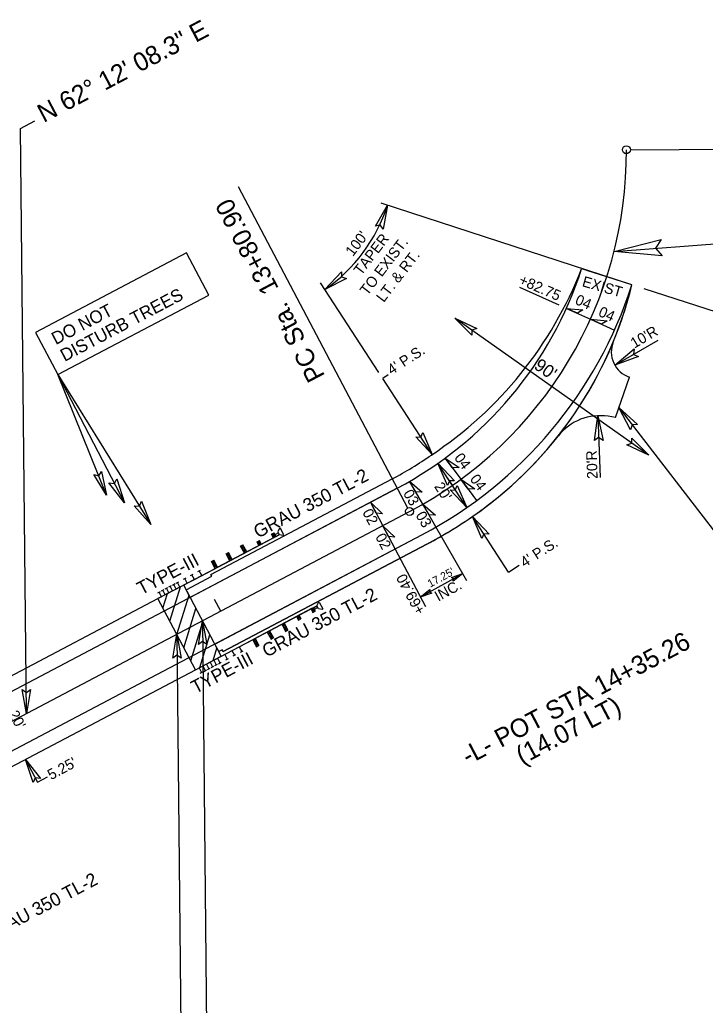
# Model space of a CAD drawing. Extents: x 1380803 to 1382221, y 595175 to 595787.
# Drawn here: x 1381652.6 to 1381912.3, y 595407.2 to 595780.6 of the extents above; entities that cross this region are included whole.
import ezdxf

# ---------------------------------------------------------------- set-up
doc = ezdxf.new("R2010")
doc.units = 0
for name, color, linetype in [('Prop Approach Slab', 7, 'Continuous'), ('Prop Approach Slab Hatching', 7, 'Continuous'), ('Prop DGN Element Guardrail', 7, 'Continuous'), ('Prop Dimension', 7, 'Continuous'), ('Prop Dimension Text', 7, 'Continuous'), ('Prop EOT', 7, 'Continuous'), ('Prop Guardrail', 7, 'Continuous'), ('Prop Guardrail Anchor Unit CELL', 7, 'Continuous'), ('Prop Horizontal Alignment', 7, 'Continuous'), ('Prop Horizontal Alignment Direction Label', 7, 'Continuous'), ('Prop Horizontal Alignment Station Label', 7, 'Continuous'), ('Prop Horizontal Alignment Tick Large', 7, 'Continuous'), ('Prop Horizontal Alignment Tick Small', 7, 'Continuous'), ('Prop Paved Shoulder', 7, 'Continuous'), ('Prop Roadway Bridge', 7, 'Continuous'), ('Prop Shade Medium', 7, 'Continuous'), ('Prop Structure Anchor Unit CELL', 7, 'Continuous'), ('Prop Superelevation  Arrow CELL', 7, 'Continuous'), ('Prop Superelevation Label', 7, 'Continuous'), ('Prop Terminator CELL', 7, 'Continuous'), ('Scratch_Level_0', 7, 'Continuous')]:
    doc.layers.add(name, color=color, linetype=linetype)

msp = doc.modelspace()

# ---------------------------------------------------------------- linework, layer by layer
at = {"layer": 'Prop Approach Slab'}
for p, q in [((1381714.7, 595566.4), (1381704.97, 595561.27)), ((1381728.92, 595539.42), (1381714.7, 595566.4)), ((1381719.19, 595534.29), (1381704.97, 595561.27)), ((1381719.19, 595534.29), (1381728.92, 595539.42))]:
    msp.add_line(p, q, dxfattribs=at)
at = {"layer": 'Prop Approach Slab Hatching'}
for p, q in [((1381706.86, 595557.68), (1381708.55, 595563.16)), ((1381709.5, 595552.68), (1381713.56, 595565.8)), ((1381712.13, 595547.68), (1381716.73, 595562.54)), ((1381714.77, 595542.67), (1381719.37, 595557.53)), ((1381717.41, 595537.67), (1381722.01, 595552.53)), ((1381720.82, 595535.15), (1381724.65, 595547.52)), ((1381725.82, 595537.79), (1381727.29, 595542.52))]:
    msp.add_line(p, q, dxfattribs=at)
at = {"layer": 'Prop DGN Element Guardrail'}
for p, q in [((1381718.79, 595568.56), (1381748.17, 595584.06)), ((1381704.97, 595561.27), (1381720.5, 595569.46)), ((1381735.78, 595543.04), (1381765.17, 595558.52)), ((1381719.19, 595534.29), (1381735.78, 595543.04))]:
    msp.add_line(p, q, dxfattribs=at)
at = {"layer": 'Prop Dimension'}
for p, q in [((1381884.53, 595680.13), (1381789.56, 595711.11)), ((1381788.69, 595646.9), (1381766.6, 595680.87)), ((1382030.06, 595633.15), (1381889.17, 595678.63)), ((1381890.93, 595615.6), (1381817.45, 595667.57)), ((1381878.08, 595649.68), (1381894.45, 595659.24)), ((1381792.14, 595646.05), (1381790.1, 595644.73)), ((1381808.88, 595615.85), (1381790.1, 595644.73)), ((1381871.63, 595630.58), (1381872.49, 595607.2)), ((1381879.63, 595633.64), (1381943.4, 595550.74)), ((1381821.94, 595595.77), (1381811.03, 595612.54)), ((1381837.82, 595571.35), (1381824.12, 595592.41)), ((1381837.82, 595571.35), (1381841.84, 595573.97)), ((1381654.72, 595500.3), (1381659.33, 595491.74)), ((1381659.33, 595491.74), (1381663.07, 595493.75))]:
    msp.add_line(p, q, dxfattribs=at)
msp.add_arc((1381732.42, 595729.75), 62.63, 304.8708, 341.9318, dxfattribs=at)
at = {"layer": 'Prop Dimension Text'}
for p, q in [((1381685.47, 595600.47), (1381667.04, 595646.14)), ((1381667.04, 595646.14), (1381692.22, 595597.54)), ((1381667.04, 595646.14), (1381702.31, 595589.32))]:
    msp.add_line(p, q, dxfattribs=at)
at = {"layer": 'Prop EOT'}
for p, q in [((1381884.53, 595680.13), (1381865.5, 595686.27)), ((1381570.94, 595484.68), (1381795.62, 595603.13)), ((1381580.27, 595466.99), (1381804.94, 595585.44))]:
    msp.add_line(p, q, dxfattribs=at)
for radius in [144, 164]:
    msp.add_arc((1381728.46, 595730.51), radius, 297.7977, 342.1091, dxfattribs=at)
at = {"layer": 'Prop Guardrail'}
for p, q in [((1381721.55, 595570.02), (1381727.08, 595572.93)), ((1381735.78, 595543.04), (1381741.3, 595545.95))]:
    msp.add_line(p, q, dxfattribs=at)
at = {"layer": 'Prop Guardrail Anchor Unit CELL'}
for p, q in [((1381748.04, 595585.7), (1381748.93, 595586.17)), ((1381748.75, 595584.36), (1381748.04, 595585.7)), ((1381748.05, 595585.7), (1381749.64, 595584.82)), ((1381748.75, 595584.36), (1381748.93, 595586.17)), ((1381749.64, 595584.82), (1381748.93, 595586.17)), ((1381750.6, 595586.16), (1381749.3, 595585.47)), ((1381751, 595587.91), (1381750.36, 595586.6)), ((1381750.36, 595586.6), (1381750.93, 595585.52)), ((1381751, 595587.91), (1381751.27, 595588.05)), ((1381752.65, 595585.45), (1381751.27, 595588.05)), ((1381749.2, 595584.59), (1381727.08, 595572.93)), ((1381742.52, 595582.79), (1381743.4, 595583.25)), ((1381743.22, 595581.44), (1381742.52, 595582.79)), ((1381742.52, 595582.79), (1381744.11, 595581.91)), ((1381743.22, 595581.44), (1381743.4, 595583.25)), ((1381743.22, 595581.44), (1381744.11, 595581.91)), ((1381744.11, 595581.91), (1381743.4, 595583.25)), ((1381748.75, 595584.36), (1381749.64, 595584.82)), ((1381749.63, 595584.83), (1381750.93, 595585.52)), ((1381750.93, 595585.52), (1381752.38, 595585.31)), ((1381752.38, 595585.31), (1381752.65, 595585.45)), ((1381730.75, 595578.3), (1381731.64, 595578.76)), ((1381732.17, 595575.61), (1381730.75, 595578.3)), ((1381732.34, 595577.42), (1381730.75, 595578.3)), ((1381731.64, 595578.76), (1381731.46, 595576.96)), ((1381733.05, 595576.08), (1381731.64, 595578.76)), ((1381736.28, 595581.21), (1381737.16, 595581.68)), ((1381737.7, 595578.53), (1381736.28, 595581.21)), ((1381737.87, 595580.34), (1381736.28, 595581.21)), ((1381737.16, 595581.68), (1381736.99, 595579.87)), ((1381736.99, 595579.87), (1381737.87, 595580.34)), ((1381736.99, 595579.87), (1381738.58, 595578.99)), ((1381738.58, 595578.99), (1381737.16, 595581.68)), ((1381737.7, 595578.53), (1381737.87, 595580.34)), ((1381737.7, 595578.53), (1381738.58, 595578.99)), ((1381725.22, 595575.38), (1381726.11, 595575.85)), ((1381726.64, 595572.7), (1381725.22, 595575.38)), ((1381726.82, 595574.51), (1381725.22, 595575.38)), ((1381726.11, 595575.85), (1381725.93, 595574.04)), ((1381725.93, 595574.04), (1381726.82, 595574.51)), ((1381727.52, 595573.16), (1381726.11, 595575.85)), ((1381726.64, 595572.7), (1381726.82, 595574.51)), ((1381731.46, 595576.96), (1381732.34, 595577.42)), ((1381731.46, 595576.96), (1381733.05, 595576.08)), ((1381732.17, 595575.61), (1381732.34, 595577.42)), ((1381732.17, 595575.61), (1381733.05, 595576.08)), ((1381725.93, 595574.04), (1381727.52, 595573.16)), ((1381726.64, 595572.7), (1381727.52, 595573.16)), ((1381765.17, 595558.52), (1381765.81, 595559.83)), ((1381765.81, 595559.83), (1381766.08, 595559.97)), ((1381766.08, 595559.97), (1381767.45, 595557.37)), ((1381763.42, 595557.61), (1381741.3, 595545.95)), ((1381762.98, 595557.38), (1381763.86, 595557.84)), ((1381762.98, 595557.38), (1381763.68, 595556.03)), ((1381762.98, 595557.38), (1381764.57, 595556.5)), ((1381763.68, 595556.03), (1381764.57, 595556.5)), ((1381763.69, 595556.03), (1381763.86, 595557.84)), ((1381763.86, 595557.84), (1381764.57, 595556.5)), ((1381763.87, 595557.83), (1381765.17, 595558.52)), ((1381765.5, 595557.88), (1381764.2, 595557.2)), ((1381765.74, 595557.43), (1381765.17, 595558.52)), ((1381767.18, 595557.22), (1381765.74, 595557.43)), ((1381767.18, 595557.22), (1381767.45, 595557.37)), ((1381751.92, 595551.55), (1381752.8, 595552.01)), ((1381752.63, 595550.2), (1381752.8, 595552.01)), ((1381752.8, 595552.01), (1381754.22, 595549.33)), ((1381757.45, 595554.46), (1381758.33, 595554.93)), ((1381757.45, 595554.46), (1381758.16, 595553.12)), ((1381757.45, 595554.46), (1381759.04, 595553.59)), ((1381758.16, 595553.12), (1381758.33, 595554.93)), ((1381758.16, 595553.12), (1381759.04, 595553.59)), ((1381758.33, 595554.93), (1381759.04, 595553.59)), ((1381746.39, 595548.63), (1381747.28, 595549.1)), ((1381746.39, 595548.63), (1381747.81, 595545.95)), ((1381746.39, 595548.63), (1381747.98, 595547.76)), ((1381747.1, 595547.29), (1381747.28, 595549.1)), ((1381747.28, 595549.1), (1381748.69, 595546.41)), ((1381751.92, 595551.55), (1381753.33, 595548.86)), ((1381751.92, 595551.55), (1381753.51, 595550.67)), ((1381752.63, 595550.2), (1381753.51, 595550.67)), ((1381754.22, 595549.33), (1381752.63, 595550.2)), ((1381753.51, 595550.67), (1381753.33, 595548.86)), ((1381753.33, 595548.86), (1381754.22, 595549.33)), ((1381740.86, 595545.72), (1381741.75, 595546.18)), ((1381740.86, 595545.72), (1381742.28, 595543.03)), ((1381740.86, 595545.72), (1381742.45, 595544.84)), ((1381741.57, 595544.37), (1381741.75, 595546.18)), ((1381741.57, 595544.37), (1381742.45, 595544.84)), ((1381741.75, 595546.18), (1381743.16, 595543.5)), ((1381742.45, 595544.84), (1381742.28, 595543.03)), ((1381747.1, 595547.29), (1381747.98, 595547.76)), ((1381748.69, 595546.41), (1381747.1, 595547.29)), ((1381747.98, 595547.76), (1381747.81, 595545.95)), ((1381747.81, 595545.95), (1381748.69, 595546.41)), ((1381743.16, 595543.5), (1381741.57, 595544.37)), ((1381742.28, 595543.03), (1381743.16, 595543.5))]:
    msp.add_line(p, q, dxfattribs=at)
at = {"layer": 'Prop Horizontal Alignment'}
msp.add_line((1381575.6, 595475.83), (1381800.28, 595594.28), dxfattribs=at)
msp.add_arc((1381728.46, 595730.51), 154, 297.7977, 0.3196, dxfattribs=at)
at = {"layer": 'Prop Horizontal Alignment Station Label'}
for p, q in [((1381652.93, 595739.45), (1381658.33, 595742.3)), ((1381655.2, 595517.79), (1381652.93, 595739.45)), ((1381883.96, 595731.38), (1382020.55, 595732.14)), ((1381799.58, 595595.61), (1381735.43, 595717.3)), ((1381877.78, 595692.81), (1382069.9, 595707.67)), ((1381721.81, 595552.91), (1381724.97, 595243.87)), ((1381712.08, 595547.78), (1381714.88, 595273.61))]:
    msp.add_line(p, q, dxfattribs=at)
for centre in [(1381882.46, 595731.37), (1381800.28, 595594.28)]:
    msp.add_circle(centre, 1.5, dxfattribs=at)
at = {"layer": 'Prop Horizontal Alignment Tick Large'}
msp.add_line((1381875.02, 595683.2), (1381867.4, 595685.66), dxfattribs=at)
at = {"layer": 'Prop Horizontal Alignment Tick Small'}
for p, q in [((1381816.58, 595604.21), (1381813.72, 595608.31)), ((1381728.72, 595556.55), (1381726.38, 595560.98))]:
    msp.add_line(p, q, dxfattribs=at)
at = {"layer": 'Prop Paved Shoulder'}
for p, q in [((1381878.32, 595629.9), (1381883.66, 595645.2)), ((1381878.32, 595629.9), (1381875.48, 595630.35)), ((1381724.97, 595570.4), (1381793.75, 595606.67)), ((1381729.66, 595541.23), (1381806.81, 595581.9))]:
    msp.add_line(p, q, dxfattribs=at)
for centre, radius, start, end in [((1381725.74, 595740.75), 150, 303.5175, 338.7034), ((1381738.83, 595715.8), 150, 304.8702, 346.2431), ((1381886.72, 595654.72), 10, 157.5584, 252.211), ((1381872.37, 595610.59), 20, 81.0479, 141.7663), ((1381728.46, 595730.51), 140, 297.7977, 304.9041), ((1381728.46, 595730.51), 168, 297.7977, 304.9041)]:
    msp.add_arc(centre, radius, start, end, dxfattribs=at)
at = {"layer": 'Prop Roadway Bridge'}
for p, q in [((1381618.82, 595515.86), (1381704.97, 595561.27)), ((1381633.05, 595488.88), (1381719.19, 595534.29))]:
    msp.add_line(p, q, dxfattribs=at)
at = {"layer": 'Prop Shade Medium'}
for p, q in [((1381795.62, 595603.13), (1381717.14, 595561.76)), ((1381726.47, 595544.07), (1381804.94, 595585.44)), ((1381717.14, 595561.76), (1381715.63, 595564.63))]:
    msp.add_line(p, q, dxfattribs=at)
for points in [[(1381715.63, 595564.63), (1381715.63, 595564.63), (1381725.31, 595569.73), (1381724.97, 595570.4), (1381793.75, 595606.67)], [(1381806.81, 595581.9), (1381729.66, 595541.23), (1381729.31, 595541.89)], [(1381729.31, 595541.89), (1381727.99, 595541.19), (1381726.47, 595544.07)]]:
    msp.add_lwpolyline(points, dxfattribs=at)
for centre, radius, start, end in [((1381728.46, 595730.51), 144, 297.7977, 342.1091), ((1381725.74, 595740.75), 150, 303.5175, 338.7034), ((1381728.46, 595730.51), 164, 297.7977, 342.1091), ((1381738.83, 595715.8), 150, 305.503, 346.2431), ((1381728.46, 595730.51), 140, 297.7977, 304.9041), ((1381728.46, 595730.51), 168, 297.7977, 305.4691)]:
    msp.add_arc(centre, radius, start, end, dxfattribs=at)
at = {"layer": 'Prop Structure Anchor Unit CELL'}
for p, q in [((1381717.35, 595570.06), (1381718.36, 595570.6)), ((1381720.11, 595571.52), (1381721.13, 595572.05)), ((1381721.55, 595570.02), (1381720.62, 595571.79)), ((1381704.97, 595561.27), (1381721.55, 595570.02)), ((1381710.44, 595566.42), (1381711.45, 595566.95)), ((1381711.82, 595567.15), (1381712.83, 595567.68)), ((1381713.26, 595565.64), (1381712.33, 595567.41)), ((1381714.58, 595568.6), (1381715.6, 595569.14)), ((1381716.02, 595567.1), (1381715.09, 595568.87)), ((1381718.79, 595568.56), (1381717.85, 595570.33)), ((1381704.91, 595563.5), (1381705.92, 595564.04)), ((1381706.35, 595562), (1381705.42, 595563.77)), ((1381706.29, 595564.23), (1381707.3, 595564.77)), ((1381707.73, 595562.73), (1381706.8, 595564.5)), ((1381707.67, 595564.96), (1381708.69, 595565.49)), ((1381709.11, 595563.46), (1381708.18, 595565.23)), ((1381709.05, 595565.69), (1381710.07, 595566.22)), ((1381710.49, 595564.19), (1381709.56, 595565.96)), ((1381711.88, 595564.92), (1381710.94, 595566.69)), ((1381719.19, 595534.29), (1381735.78, 595543.04)), ((1381733.01, 595541.58), (1381733.94, 595539.81)), ((1381735.78, 595543.04), (1381736.71, 595541.27)), ((1381736.2, 595541), (1381737.21, 595541.53)), ((1381724.72, 595537.21), (1381725.65, 595535.44)), ((1381726.1, 595537.94), (1381727.03, 595536.17)), ((1381727.48, 595538.66), (1381728.42, 595536.9)), ((1381727.91, 595536.63), (1381728.92, 595537.16)), ((1381730.25, 595540.12), (1381731.18, 595538.35)), ((1381730.67, 595538.09), (1381731.69, 595538.62)), ((1381733.44, 595539.54), (1381734.45, 595540.08)), ((1381720.57, 595535.02), (1381721.5, 595533.25)), ((1381721, 595532.98), (1381722.01, 595533.52)), ((1381721.95, 595535.75), (1381722.89, 595533.98)), ((1381722.38, 595533.71), (1381723.39, 595534.25)), ((1381723.34, 595536.48), (1381724.27, 595534.71)), ((1381723.76, 595534.44), (1381724.78, 595534.98)), ((1381725.14, 595535.17), (1381726.16, 595535.7)), ((1381726.53, 595535.9), (1381727.54, 595536.43))]:
    msp.add_line(p, q, dxfattribs=at)
at = {"layer": 'Prop Superelevation  Arrow CELL'}
for points in [[(1381859.7, 595671.23), (1381865.99, 595670.66), (1381863.93, 595669.38)], [(1381868.81, 595667.12), (1381875.11, 595666.55), (1381873.05, 595665.26)], [(1381813.82, 595614.54), (1381819.04, 595610.96), (1381816.61, 595610.85)], [(1381800.33, 595605.72), (1381805.09, 595601.57), (1381802.67, 595601.74)], [(1381819.75, 595606.49), (1381824.96, 595602.9), (1381822.54, 595602.79)], [(1381785.44, 595597.77), (1381790.05, 595593.43), (1381787.64, 595593.69)], [(1381805.32, 595597.06), (1381810.08, 595592.9), (1381807.66, 595593.07)], [(1381790.11, 595588.92), (1381794.71, 595584.58), (1381792.3, 595584.85)]]:
    msp.add_lwpolyline(points, close=True, dxfattribs=at)
at = {"layer": 'Prop Superelevation Label'}
for p, q in [((1381841.92, 595679.26), (1381856.82, 595672.53)), ((1381859.7, 595671.23), (1381868.81, 595667.12)), ((1381868.81, 595667.12), (1381877.92, 595663)), ((1381813.82, 595614.54), (1381819.75, 595606.49)), ((1381805.32, 595597.06), (1381800.33, 595605.72)), ((1381819.75, 595606.49), (1381825.68, 595598.43)), ((1381785.44, 595597.77), (1381790.11, 595588.92)), ((1381822.05, 595568), (1381805.32, 595597.06)), ((1381790.11, 595588.92), (1381806.28, 595558.25)), ((1381804.36, 595561.89), (1381820.46, 595570.77))]:
    msp.add_line(p, q, dxfattribs=at)
at = {"layer": 'Prop Terminator CELL'}
for points in [[(1381787.35, 595702.45), (1381791.96, 595710.33), (1381790.28, 595701.29), (1381789.19, 595702.93)], [(1381895.96, 595691.11), (1381877.78, 595692.81), (1381895.58, 595697.4), (1381893.53, 595694.03)], [(1381667.04, 595646.14), (1381724.25, 595676.3), (1381715.83, 595692.28), (1381658.62, 595662.12)], [(1381776.34, 595682.57), (1381768.23, 595678.37), (1381774.48, 595685.11), (1381774.53, 595683.14)], [(1381823.9, 595661.1), (1381817.45, 595667.57), (1381825.76, 595663.65), (1381823.9, 595663.01)], [(1381886.99, 595653.01), (1381878.08, 595649.68), (1381885.38, 595655.87), (1381885.19, 595653.83)], [(1381870.36, 595621.15), (1381871.63, 595630.58), (1381873.64, 595621.22), (1381871.93, 595622.36)], [(1381884.06, 595625.23), (1381879.63, 595633.64), (1381886.69, 595627.19), (1381884.64, 595627.12)], [(1381805.29, 595624.24), (1381808.88, 595615.85), (1381802.62, 595622.57), (1381804.59, 595622.48)], [(1381884.48, 595622.06), (1381890.93, 595615.6), (1381882.62, 595619.52), (1381884.48, 595620.16)], [(1381814.68, 595604.17), (1381811.03, 595612.54), (1381817.34, 595605.85), (1381815.38, 595605.94)], [(1381683.54, 595609.39), (1381685.47, 595600.47), (1381680.6, 595608.26), (1381682.51, 595607.79)], [(1381689.34, 595606.61), (1381692.22, 595597.54), (1381686.4, 595605.15), (1381688.43, 595604.85)], [(1381818.33, 595604.15), (1381821.94, 595595.77), (1381815.66, 595602.48), (1381817.63, 595602.39)], [(1381698.74, 595598.14), (1381702.31, 595589.32), (1381695.92, 595596.45), (1381697.97, 595596.31)], [(1381827.73, 595584.02), (1381824.12, 595592.41), (1381830.4, 595585.69), (1381828.43, 595585.78)], [(1381816.13, 595569.32), (1381820.46, 595570.77), (1381816.85, 595567.92), (1381816.98, 595568.89)], [(1381808.67, 595563.39), (1381804.36, 595561.89), (1381807.93, 595564.78), (1381807.81, 595563.8)], [(1381720.35, 595543.9), (1381721.81, 595552.91), (1381723.5, 595543.88), (1381721.89, 595545.01)], [(1381710.61, 595538.77), (1381712.08, 595547.78), (1381713.76, 595538.75), (1381712.15, 595539.88)], [(1381656.66, 595526.81), (1381655.2, 595517.79), (1381653.51, 595526.83), (1381655.12, 595525.69)], [(1381657.62, 595491.64), (1381654.72, 595500.3), (1381660.42, 595493.09), (1381658.46, 595493.35)]]:
    msp.add_lwpolyline(points, close=True, dxfattribs=at)

# ---------------------------------------------------------------- texts
at = {"layer": 'Prop Dimension'}
for s, rotation, p in [("100'", 52.8697, (1381778.83, 595690.67)), ('TAPER', 52.49, (1381781.96, 595683.48)), ('TO EXIST.', 52.49, (1381784.3, 595675.85)), ('LT. & RT.', 52.49, (1381790.49, 595673.25)), ("10'R", 30.3011, (1381885.47, 595655.97)), ("4' P.S.", 33.0328, (1381793.48, 595645.89)), ("20'R", 92.1261, (1381871.57, 595606.7)), ("20'", 303.0328, (1381809.46, 595603.77)), ("4' P.S.", 33.0328, (1381843.87, 595572.93)), ("20'", 298.2777, (1381648.25, 595517.61)), ("5.25'", 28.2777, (1381664.46, 595492.45))]:
    msp.add_text(s, height=4, rotation=rotation, dxfattribs=at).set_placement(p)
at = {"layer": 'Prop Dimension Text'}
for s, rotation, p in [('DISTURB TREES', 27.7977, (1381669.58, 595650.94)), ('DO NOT', 27.7977, (1381666.23, 595657.31)), ("90'", 324.7278, (1381847.09, 595648.7))]:
    msp.add_text(s, height=4.8, rotation=rotation, dxfattribs=at).set_placement(p)
at = {"layer": 'Prop Guardrail Anchor Unit CELL'}
for p in [(1381742.85, 595584.02), (1381746.12, 595538.89), (1381640.22, 595430.96)]:
    msp.add_text('GRAU 350 TL-2', height=5, rotation=27.7977, dxfattribs=at).set_placement(p)
at = {"layer": 'Prop Horizontal Alignment Direction Label'}
msp.add_text('N 62%%d 12\' 08.3" E', height=7, rotation=27.7977, dxfattribs=at).set_placement((1381661.67, 595741.45))
at = {"layer": 'Prop Horizontal Alignment Station Label'}
msp.add_text('PC Sta.  13+80.90', height=7, rotation=117.7977, dxfattribs=at).set_placement((1381768.37, 595645.65))
at = {"layer": 'Prop Structure Anchor Unit CELL'}
for p in [(1381698.67, 595562.52), (1381719.2, 595525.1)]:
    msp.add_text('TYPE-III', height=5, rotation=27.7977, dxfattribs=at).set_placement(p)
at = {"layer": 'Prop Superelevation Label'}
for s, height, rotation, p in [('+82.75', 4, 336.3978, (1381841.35, 595680.59)), ('EXIST', 4, 343.8566, (1381865.39, 595679.7)), ('04', 4, 336.3978, (1381862.68, 595673.05)), ('04', 4, 336.3978, (1381871.51, 595668.5)), ('04', 4, 307.0616, (1381817.01, 595614.56)), ('04', 4, 307.0616, (1381822.95, 595606.54)), ('03', 4, 300.4726, (1381797.71, 595601.15)), ('02', 4, 298.2777, (1381782.28, 595593.98)), ('03', 4, 300.4726, (1381802.45, 595592.87)), ('02', 4, 298.2777, (1381787.19, 595584.7)), ("17.25'", 3, 28.8548, (1381808.11, 595565.38)), ('+69.40', 4, 118.2777, (1381806.38, 595556.58)), ('INC.', 4, 28.8548, (1381811.16, 595560.09))]:
    msp.add_text(s, height=height, rotation=rotation, dxfattribs=at).set_placement(p)
at = {"layer": 'Scratch_Level_0'}
for s, p in [('-L- POT STA 14+35.26', (1381822.42, 595498.11)), ('       (14.07 LT)', (1381826.85, 595489.71))]:
    msp.add_text(s, height=7, rotation=27.7977, dxfattribs=at).set_placement(p)

doc.saveas('drawing.dxf')
